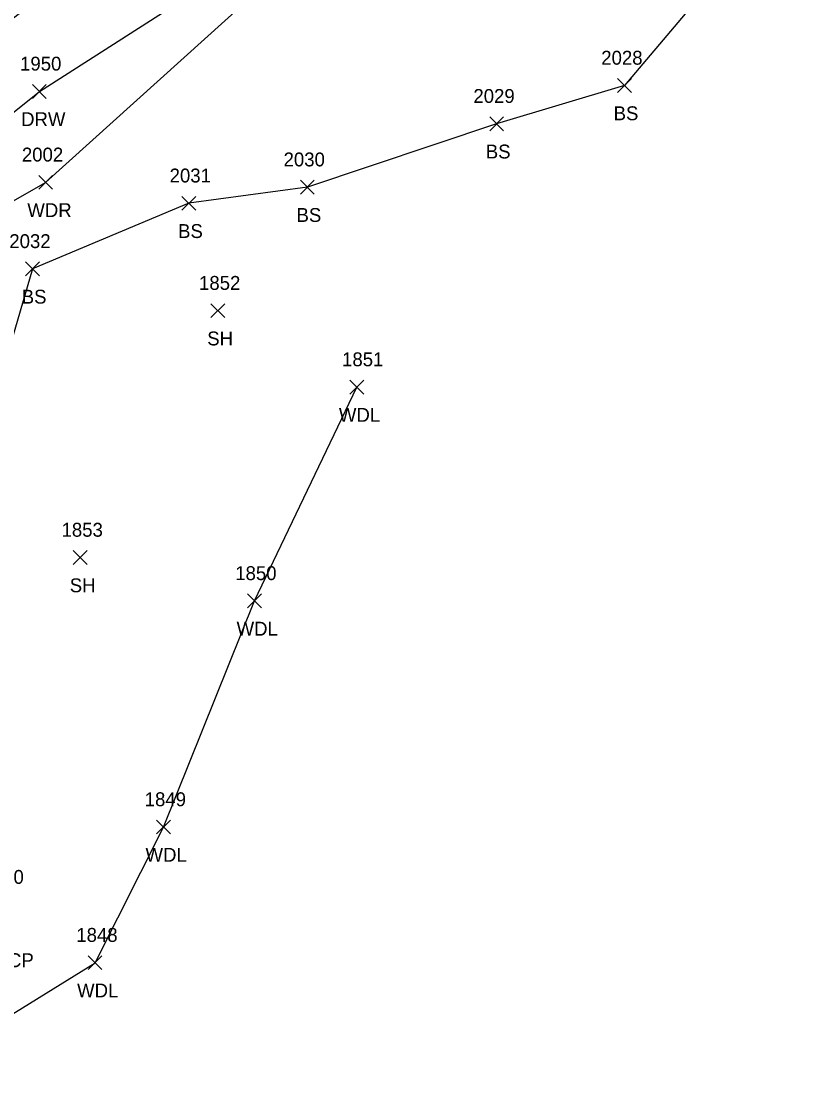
# Model space of a CAD drawing. Extents: x 462930 to 463548, y 29607 to 30453.
# Drawn here: x 463386.81 to 463421.6, y 30129.25 to 30175.85 of the extents above; entities that cross this region are included whole.
import ezdxf

# ---------------------------------------------------------------- set-up
doc = ezdxf.new("R2010")
doc.units = 0
for name, color, linetype in [('D_C', 7, 'Continuous'), ('D_I', 7, 'Continuous'), ('L_A', 7, 'Continuous'), ('L_I', 7, 'Continuous'), ('L_TIC', 7, 'Continuous'), ('LAWA', 7, 'Continuous'), ('LELB', 7, 'Continuous'), ('R_A', 7, 'Continuous'), ('R_I', 7, 'Continuous'), ('R_TIC', 7, 'Continuous'), ('RDW', 7, 'Continuous')]:
    doc.layers.add(name, color=color, linetype=linetype)

msp = doc.modelspace()

# ---------------------------------------------------------------- linework, layer by layer
at = {"layer": 'L_TIC'}
for points in [[(463412.984, 30172.721), (463413.594, 30173.331)], [(463413.594, 30172.721), (463412.984, 30173.331)], [(463407.373, 30171.042), (463407.983, 30171.652)], [(463407.983, 30171.042), (463407.373, 30171.652)], [(463387.575, 30168.47), (463388.185, 30169.08)], [(463388.185, 30168.47), (463387.575, 30169.08)], [(463399.064, 30168.257), (463399.674, 30168.867)], [(463399.674, 30168.257), (463399.064, 30168.867)], [(463393.863, 30167.551), (463394.473, 30168.161)], [(463394.473, 30167.551), (463393.863, 30168.161)], [(463386.999, 30164.671), (463387.609, 30165.281)], [(463387.609, 30164.671), (463386.999, 30165.281)], [(463395.13, 30162.837), (463395.74, 30163.447)], [(463395.74, 30162.837), (463395.13, 30163.447)], [(463401.236, 30159.484), (463401.846, 30160.094)], [(463401.846, 30159.484), (463401.236, 30160.094)], [(463389.094, 30152.002), (463389.704, 30152.612)], [(463389.704, 30152.002), (463389.094, 30152.612)], [(463396.745, 30150.097), (463397.355, 30150.707)], [(463397.355, 30150.097), (463396.745, 30150.707)], [(463392.747, 30140.174), (463393.357, 30140.784)], [(463393.357, 30140.174), (463392.747, 30140.784)], [(463389.743, 30134.219), (463390.353, 30134.829)], [(463390.353, 30134.219), (463389.743, 30134.829)]]:
    msp.add_lwpolyline(points, dxfattribs=at)
at = {"layer": 'LAWA'}
for points in [[(463359.706, 30142.039), (463364.322, 30149.214), (463366.2, 30150.874), (463372.054, 30151.198), (463374.44, 30152.677), (463375.941, 30153.694), (463376.334, 30154.745), (463378.034, 30157.16), (463384.03, 30166.577), (463387.88, 30168.775), (463397.819, 30177.75)], [(463380.658, 30129.253), (463385.01, 30131.404), (463390.048, 30134.524), (463393.052, 30140.479), (463397.05, 30150.402), (463401.541, 30159.789)]]:
    msp.add_lwpolyline(points, dxfattribs=at)
at = {"layer": 'LELB'}
msp.add_lwpolyline([(463421.6, 30182.858), (463413.289, 30173.026), (463407.678, 30171.347), (463399.369, 30168.562), (463394.168, 30167.856), (463387.304, 30164.976), (463384.785, 30156.391), (463383.903, 30152.112)], dxfattribs=at)
at = {"layer": 'R_TIC'}
for points in [[(463387.3, 30172.462), (463387.91, 30173.072)], [(463387.91, 30172.462), (463387.3, 30173.072)]]:
    msp.add_lwpolyline(points, dxfattribs=at)
at = {"layer": 'RDW'}
msp.add_lwpolyline([(463370.611, 30158.273), (463377.737, 30164.866), (463387.605, 30172.767), (463398.297, 30179.61), (463406.605, 30184.823), (463404.673, 30188.349), (463395.336, 30182.896), (463385.655, 30175.354), (463377.627, 30169.204)], dxfattribs=at)

# ---------------------------------------------------------------- texts
at = {"layer": 'D_C'}
msp.add_text('460VCP', height=0.6096, dxfattribs=at).set_placement((463384.322, 30134.327))
at = {"layer": 'D_I'}
msp.add_text('1870', height=0.6096, dxfattribs=at).set_placement((463385.109, 30137.984))
at = {"layer": 'L_A'}
for s, p in [('BS', (463412.814, 30171.502)), ('BS', (463407.203, 30169.823)), ('WDR', (463387.076, 30167.251)), ('BS', (463398.894, 30167.038)), ('BS', (463393.693, 30166.332)), ('BS', (463386.829, 30163.452)), ('SH', (463394.974, 30161.618)), ('WDL', (463400.754, 30158.265)), ('SH', (463388.938, 30150.783)), ('WDL', (463396.263, 30148.878)), ('WDL', (463392.265, 30138.955)), ('WDL', (463389.261, 30133))]:
    msp.add_text(s, height=0.6096, dxfattribs=at).set_placement(p)
at = {"layer": 'L_I'}
for s, p in [('2028', (463412.271, 30173.94)), ('2029', (463406.658, 30172.261)), ('2002', (463386.838, 30169.689)), ('2030', (463398.325, 30169.476)), ('2031', (463393.323, 30168.77)), ('2032', (463386.286, 30165.89)), ('1852', (463394.614, 30164.056)), ('1851', (463400.893, 30160.703)), ('1853', (463388.578, 30153.221)), ('1850', (463396.203, 30151.316)), ('1849', (463392.229, 30141.393)), ('1848', (463389.227, 30135.438))]:
    msp.add_text(s, height=0.6096, dxfattribs=at).set_placement(p)
at = {"layer": 'R_A'}
msp.add_text('DRW', height=0.6096, dxfattribs=at).set_placement((463386.803, 30171.243))
at = {"layer": 'R_I'}
msp.add_text('1950', height=0.6096, dxfattribs=at).set_placement((463386.758, 30173.681))

doc.saveas('drawing.dxf')
